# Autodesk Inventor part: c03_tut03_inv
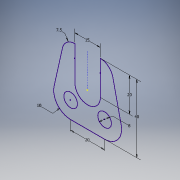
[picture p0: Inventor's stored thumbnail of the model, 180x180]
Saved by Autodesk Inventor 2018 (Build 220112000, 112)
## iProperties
Created: 2017-04
Part Number: c03_tut03_inv
Material: Generic
Document SubType Name: Modeling
Designer: CADCIM 00
Density: 1 g/cm^3
Appearance: Default
Author: CADCIM 00
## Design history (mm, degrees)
sketch "Sketch1"
  geometry: L1 (-10, -20)-(10, -20); L2 (19.756, -7.805)-(14.817, 14.146); L3 (7.5, 20)-(7.5, 0); L4 (-7.5, 0)-(-7.5, 20); L5 (-14.817, 14.146)-(-19.756, -7.805); L6 (0, 0)-(0, 20); C1 r 4 at (-10, -10); C2 r 4 at (10, -10); A1 r 10 centre (10, -10) between (10, -20) and (19.756, -7.805); A2 r 7.5 centre (7.5, 12.5) between (14.817, 14.146) and (7.5, 20); A3 r 7.5 centre (0, 0) between (-7.5, 0) and (7.5, 0); A4 r 7.5 centre (-7.5, 12.5) between (-7.5, 20) and (-14.817, 14.146); A5 r 10 centre (-10, -10) between (-19.756, -7.805) and (-10, -20); 1 further point
  constraints: 12 end point, 10 point on circle, 8 tangent, 7 centre point, 3 coincident, 3 equal radius, 2 equal length, 2 point on line, 1 horizontal, 1 horizontal alignment, 1 parallel, 1 perpendicular, 1 vertical, 3 other
  dimensions: "d0" = 20 distance of L1.start L1.end; "d1" = 7.5 radius of A2; "d2" = 10 radius of A1; "d3" = 15 distance between parallel lines of L4 L3; "d5" = 40 distance from line of L1 L4.end; "d6" = 20 distance of L4.start L4.end; "d7" = 8 diameter of C1
